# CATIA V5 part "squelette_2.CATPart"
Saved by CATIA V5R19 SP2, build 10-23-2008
Part number: squelette_2
Publications: "Point.1", "Point.2", "Point.3", "Droite.1", "Droite.2", "Droite.3", "Point.8", "Point.9", "Point.10", "Plan.1", "Droite.6"
Bounding box of the stored display mesh (mm): x -10 to 10, y -58 to 80, z -6 to 3
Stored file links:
  M:\EU_thinkMotion\IAO_2010\iao\IAO_MMS_Groupe2\IAO_MMS_Groupe2\sdubois\sdubois\sdubois\IAO_mecanisme\squelette_2.CATPart
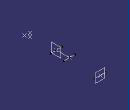
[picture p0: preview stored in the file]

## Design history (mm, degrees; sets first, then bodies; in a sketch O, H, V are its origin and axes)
Set1
  Point1: (0, 0, 0)
  Point2: (0, 24, 0)
  Point3: (0, 80, 0)
  Line1: type Normal, RefPoint Point3, RefSkin yz-plane, Start -10, End 10
  Line2: type Normal, RefPoint Point2, RefSkin yz-plane, Start -10, End 10
  Line3: type PtDir, RefPoint Point1, Direction yz-plane, Start -10, End 10
  Point4: (0, -48, 3)
  Point5: (0, -48, -3)
  Point6: (0, -58, -6)
  Plane1: type OffsetPt, RefPlane zx-plane, RefPoint Point3
  Line4: type PtPt, FirstPoint Point1, SecondPoint Point2
Body1 (main body)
